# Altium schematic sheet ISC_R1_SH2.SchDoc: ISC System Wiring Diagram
size B; DrawnBy: Filiberto Clara; Engineer: Filiberto Clara; Organization: LIGO Laboratory; Address1: California Institute of Technology; Address2: Massachusetts Institute of Technology; SheetNumber: 11; SheetTotal: 39
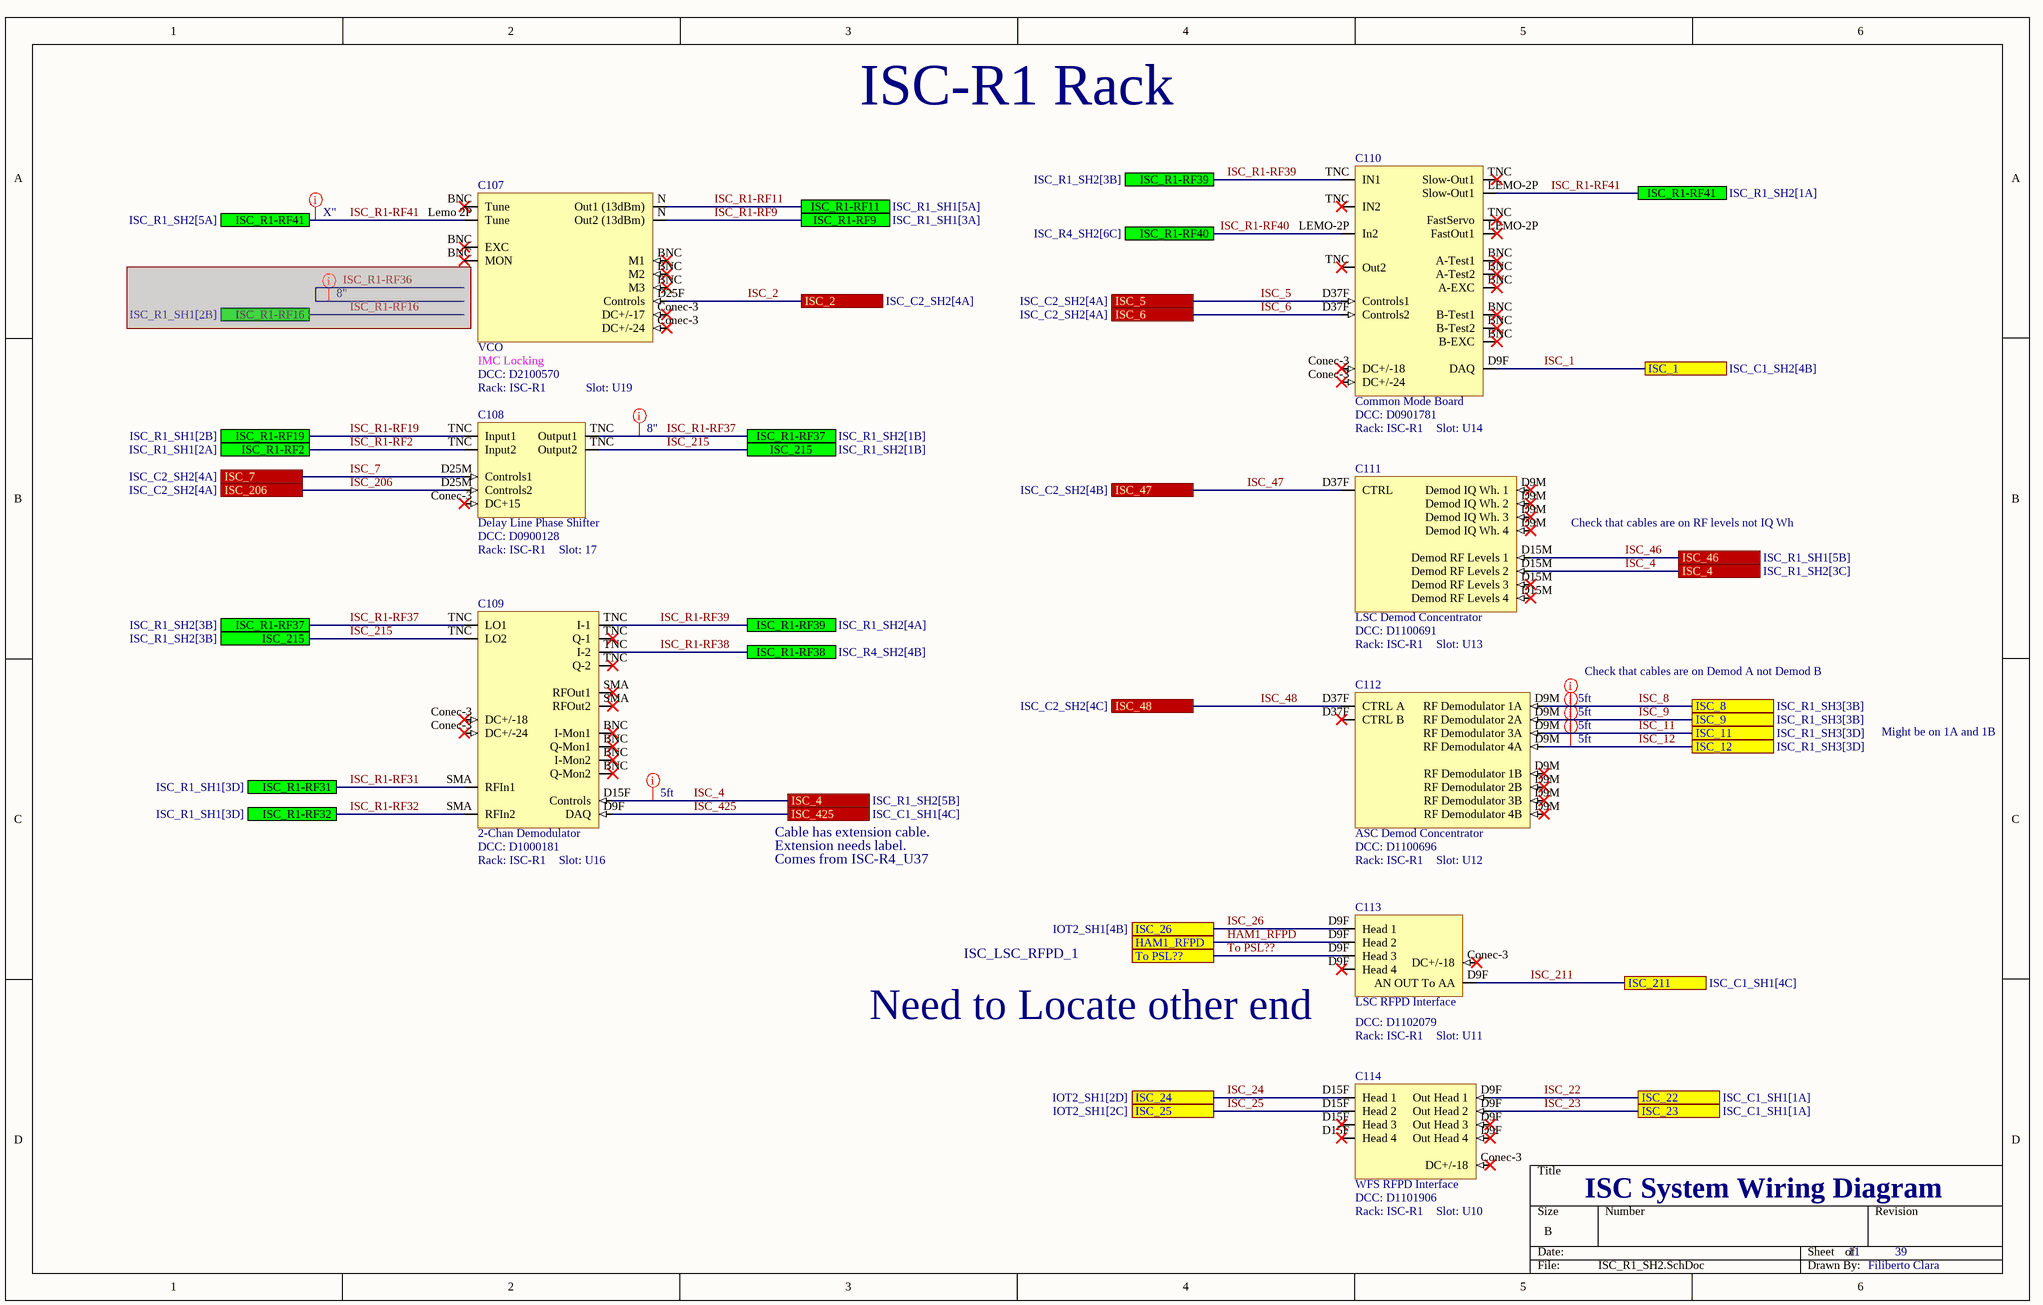
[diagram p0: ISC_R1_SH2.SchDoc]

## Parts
C107  VCO  DCC: D2100570  Rack: ISC-R1  Slot: U19
C108  Delay Line Phase Shifter  DCC: D0900128  Rack: ISC-R1  Slot: 17
C109  2-Chan Demodulator  DCC: D1000181  Rack: ISC-R1  Slot: U16
C110  Common Mode Board  DCC: D0901781  Rack: ISC-R1  Slot: U14
C111  LSC Demod Concentrator  DCC: D1100691  Rack: ISC-R1  Slot: U13
C112  ASC Demod Concentrator  DCC: D1100696  Rack: ISC-R1  Slot: U12
C113  LSC RFPD Interface  DCC: D1102079  Rack: ISC-R1  Slot: U11
C114  WFS RFPD Interface  DCC: D1101906  Rack: ISC-R1  Slot: U10

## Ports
HAM1_RFPD, ISC_1 (see ISC_C1_SH2[4B]), ISC_2 (see ISC_C2_SH2[4A]), ISC_4 (see ISC_R1_SH2[3C]), ISC_4 (see ISC_R1_SH2[5B]), ISC_5 (see ISC_C2_SH2[4A]), ISC_6 (see ISC_C2_SH2[4A]), ISC_7 (see ISC_C2_SH2[4A]), ISC_8 (see ISC_R1_SH3[3B]), ISC_9 (see ISC_R1_SH3[3B]), ISC_11 (see ISC_R1_SH3[3D]), ISC_12 (see ISC_R1_SH3[3D]), ISC_22 (see ISC_C1_SH1[1A]), ISC_23 (see ISC_C1_SH1[1A]), ISC_24 (see IOT2_SH1[2D]), ISC_25 (see IOT2_SH1[2C]), ISC_26 (see IOT2_SH1[4B]), ISC_46 (see ISC_R1_SH1[5B]), ISC_47 (see ISC_C2_SH2[4B]), ISC_48 (see ISC_C2_SH2[4C]), ISC_206 (see ISC_C2_SH2[4A]), ISC_211 (see ISC_C1_SH1[4C]), ISC_215 (see ISC_R1_SH2[1B]), ISC_215 (see ISC_R1_SH2[3B]), ISC_425 (see ISC_C1_SH1[4C]), ISC_R1-RF2 (see ISC_R1_SH1[2A]), ISC_R1-RF9 (see ISC_R1_SH1[3A]), ISC_R1-RF11 (see ISC_R1_SH1[5A]), ISC_R1-RF16 (see ISC_R1_SH1[2B]), ISC_R1-RF19 (see ISC_R1_SH1[2B]), ISC_R1-RF31 (see ISC_R1_SH1[3D]), ISC_R1-RF32 (see ISC_R1_SH1[3D]), ISC_R1-RF37 (see ISC_R1_SH2[1B]), ISC_R1-RF37 (see ISC_R1_SH2[3B]), ISC_R1-RF38 (see ISC_R4_SH2[4B]), ISC_R1-RF39 (see ISC_R1_SH2[3B]), ISC_R1-RF39 (see ISC_R1_SH2[4A]), ISC_R1-RF40 (see ISC_R4_SH2[6C]), ISC_R1-RF41 (see ISC_R1_SH2[1A]), ISC_R1-RF41 (see ISC_R1_SH2[5A]), To PSL??

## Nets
HAM1_RFPD: C113.D9F(Head_2) ; port HAM1_RFPD
ISC_1: C110.D9F(DAQ) ; port ISC_1
ISC_2: C107.D25F(Controls) ; port ISC_2
ISC_4: C109.D15F(Controls) C111.D15M(Demod_RF_Levels_2) ; port ISC_4
ISC_5: C110.D37F(Controls1) ; port ISC_5
ISC_6: C110.D37F(Controls2) ; port ISC_6
ISC_7: C108.D25M(Controls1) ; port ISC_7
ISC_8: C112.D9M(RF_Demodulator_1A) ; port ISC_8
ISC_9: C112.D9M(RF_Demodulator_2A) ; port ISC_9
ISC_11: C112.D9M(RF_Demodulator_3A) ; port ISC_11
ISC_12: C112.D9M(RF_Demodulator_4A) ; port ISC_12
ISC_22: C114.D9F(Out_Head_1) ; port ISC_22
ISC_23: C114.D9F(Out_Head_2) ; port ISC_23
ISC_24: C114.D15F(Head_1) ; port ISC_24
ISC_25: C114.D15F(Head_2) ; port ISC_25
ISC_26: C113.D9F(Head_1) ; port ISC_26
ISC_46: C111.D15M(Demod_RF_Levels_1) ; port ISC_46
ISC_47: C111.D37F(CTRL) ; port ISC_47
ISC_48: C112.D37F(CTRL_A) ; port ISC_48
ISC_206: C108.D25M(Controls2) ; port ISC_206
ISC_211: C113.D9F(AN_OUT_To_AA) ; port ISC_211
ISC_215: C108.TNC(Output2) C109.TNC(LO2) ; port ISC_215
ISC_425: C109.D9F(DAQ) ; port ISC_425
ISC_R1-RF2: C108.TNC(Input2) ; port ISC_R1-RF2
ISC_R1-RF9: C107.N(Out2_(13dBm)) ; port ISC_R1-RF9
ISC_R1-RF11: C107.N(Out1_(13dBm)) ; port ISC_R1-RF11
ISC_R1-RF19: C108.TNC(Input1) ; port ISC_R1-RF19
ISC_R1-RF31: C109.SMA(RFOut1) ; port ISC_R1-RF31
ISC_R1-RF32: C109.SMA(RFIn2) ; port ISC_R1-RF32
ISC_R1-RF37: C108.TNC(Output1) C109.TNC(LO1) ; port ISC_R1-RF37
ISC_R1-RF38: C109.TNC(I-2) ; port ISC_R1-RF38
ISC_R1-RF39: C109.TNC(I-1) C110.TNC(IN1) ; port ISC_R1-RF39
ISC_R1-RF40: C110.LEMO-2P(In2) ; port ISC_R1-RF40
ISC_R1-RF41: C107.Lemo_2P(Tune) C110.LEMO-2P(Slow-Out1) ; port ISC_R1-RF41
To PSL??: C113.D9F(Head_3) ; port To PSL??

Not connected (* = marked no-connect by the designer): C107 BNC(Tune)* Conec-3(DC+/-17)*; C108 Conec-3(DC+15)*; C109 BNC(I-Mon1)* Conec-3(DC+/-18)*; C110 BNC(A-Test1)* Conec-3(DC+/-18)*; C111 D9M(Demod_IQ_Wh._1)*; C113 Conec-3(DC+/-18)*; C114 Conec-3(DC+/-18)*

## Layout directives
Length: 5ft: ISC_4, ISC_8, ISC_9, ISC_11, ISC_12
Length: 8": (no net found under the mark), ISC_R1-RF37
Length: X": ISC_R1-RF41

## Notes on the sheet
- ISC-R1 Rack
- (near C107) IMC Locking
- Check that cables are on RF levels not IQ Wh
- Check that cables are on Demod A not Demod B
- Might be on 1A and 1B
- Cable has extension cable.
- Extension needs label.
- Comes from ISC-R4_U37
- ISC_LSC_RFPD_1
- (near C113) Need to Locate other end

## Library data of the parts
C107 = VCONew: New VCO; Serial: Sxxxxxxx; System: ISC
C108 = DelayLinePhaseShifter: Serial: Sxxxxxxx; System: ISC
C109 = 2-Chan Demod: Serial: Sxxxxxxx; System: ISC
C110 = CommonModeBoard: Serial: Sxxxxxxx; System: ISC
C111 = LSC Demod Concentrator: Serial: Sxxxxxxx; System: ISC
C112 = ASC Demod Concentrator: Serial: Sxxxxxxx; System: ISC
C113 = LSC RFPD Interface: Serial: Sxxxxxxx; System: ISC
C114 = WFS RFPD Interface: Serial: Sxxxxxxx; System: ISC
